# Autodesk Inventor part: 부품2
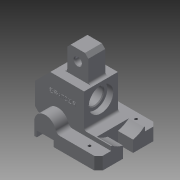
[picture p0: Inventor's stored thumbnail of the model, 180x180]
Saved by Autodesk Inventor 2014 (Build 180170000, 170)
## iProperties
Created: 2016-11
Part Number: 부품2
Material: 일반
Document SubType Name: Modeling
Designer: net
Density: 1 g/cm^3
Appearance: 기본값
Author: net
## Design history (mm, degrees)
sketch "스케치1"
  geometry: L1 (31, 18)-(-9, 18); L2 (-9, 18)-(-27, 0); L3 (-27, 0)-(-27, -30); L4 (-27, -30)-(31, -30); L5 (31, -30)-(31, 18); L6 (31, -10)-(31, -30); L7 (63, -22)-(31, -22); L8 (31, -22)-(31, -42); L9 (31, -42)-(63, -42); L10 (63, -42)-(63, -22); 1 further point
  constraints: 20 end point, 3 parallel, 3 perpendicular, 2 horizontal, 1 point on line
  dimensions: "d0" = 45 deg angle of L1 L2; "d1" = 30 distance from line of L4 point (0, 0); "d2" = 48 distance of L4.end L1.start; "d3" = 58 distance of L3.end L4.end; "d4" = 27 distance from line of point (0, 0) L3; "d5" = 18 horizontal distance of L1.end L2.end; "d31" = 42 distance from line of L9 point (0, 0); "d32" = 90 distance between parallel lines of L3 L10; "d33" = 20 distance of L9.end L7.start
extrude "돌출1" new body sketch "스케치1" stored distance "d6" = 40; taper "d7" = 0 deg
sketch "스케치2"
  geometry: L1 (-13, -27)-(-13, -42); L2 (-13, -42)-(-10, -42); L3 (-10, -42)-(-10, -35); L4 (-10, -35)-(10, -35); L5 (10, -35)-(10, -42); L6 (10, -42)-(63, -42); L7 (63, -42)-(63, -27); L8 (63, -27)-(17.292, -27); A1 r 13 centre (0, -27) between (12.488, -23.389) and (-13, -27); A2 r 5 centre (17.292, -22) between (12.488, -23.389) and (17.292, -27); 1 further point
  constraints: 16 end point, 5 parallel, 4 point on circle, 3 perpendicular, 3 tangent, 2 centre point, 1 horizontal alignment, 1 vertical, 1 vertical alignment
  dimensions: "d8" = 5 radius of A2; "d9" = 20 distance of L3.end L4.end; "d10" = 3 distance of L1.end L2.end; "d11" = 7 distance of L2.end L3.end; "d12" = 13 radius of A1; "d13" = 15 distance between parallel lines of L6 L8; "d14" = 63 distance from line of L7 A1.centre; "d15" = 42 distance from line of point (0, 0) L6
extrude "돌출2" join sketch "스케치2" stored distance "d16" = 70; taper "d17" = 0 deg
sketch "스케치3"
  geometry: L1 (63, -22)-(63, -42) reference; L2 (63, -42)-(10, -42) reference; L3 (10, -42)-(10, -35) reference; L4 (10, -35)-(-10, -35) reference; L5 (-10, -35)-(-10, -42) reference; L6 (-10, -42)-(-13, -42) reference; L7 (-13, -42)-(-13, -30) reference; L8 (-13, -30)-(-27, -30) reference; L9 (-27, -30)-(-27, 0) reference; L10 (-27, 0)-(-9, 18) reference; L11 (-9, 18)-(31, 18) reference; L12 (31, 18)-(31, -22) reference; L13 (1, 18)-(1, 44); L14 (1, 44)-(5, 48); L15 (5, 48)-(22, 48); L16 (22, 48)-(26, 44); L17 (26, 44)-(26, 18); L18 (31, -22)-(63, -22) reference; 1 further point
  constraints: 10 end point, 3 perpendicular, 2 point on line, 1 parallel
  dimensions: "d18" = 4 horizontal distance of L13.end L14.end; "d19" = 4 horizontal distance of L15.end L16.end; "d20" = 4 horizontal distance of L13.end L14.end; "d21" = 25 distance between parallel lines of L17 L13; "d22" = 5 distance between parallel lines of L17 L12; "d23" = 90 distance between parallel lines of L2 L15
extrude "돌출3" join sketch "스케치3" stored distance "d24" = 20; taper "d25" = 0 deg
sketch "스케치5"
  geometry: L1 (0, 0)-(40, 0) reference; L2 (55, -20)-(-15, -20) reference; L3 (14, -6.373)-(14, -20); L4 (26, -6.373)-(26, -20); A1 r 29 centre (20, 22) between (1.106, 0) and (14, -6.373); A2 r 29 centre (20, 22) between (26, -6.373) and (38.894, 0); 1 further point
  constraints: 4 end point, 4 point on circle, 4 point on line, 2 centre point, 2 perpendicular, 1 coincident
  dimensions: "d35" = 12 distance between parallel lines of L3 L4; "d36" = 6 distance from line of point (20, 22) L3; "d37" = 29 radius of A1; "d38" = 29 radius of A2
extrude "돌출4" cut sketch "스케치5" distance "d39" = 18; taper "d40" = 0 deg
sketch "스케치6"
  geometry: 1 further point
hole "구멍1" sketch "스케치6" at (-20, 22) diameter "d41" = 20; stored, may be unused: countersink angle "d45" = 90 deg, drill point angle "d47" = 118 deg; dims "d42" = 6, "d43" = 29, "d44" = 7, "d46" = 8
sketch "스케치7"
  geometry: L1 (1, 44)-(1, 18) reference; 2 further points
  dimensions: "d48" = 12.5 distance from line of point (13.5, 35) L1; "d49" = 35 vertical distance of point (0, 0) point (13.5, 35)
hole "구멍2" sketch "스케치7" at (13.5, 35) diameter "d50" = 8; stored, may be unused: countersink angle "d54" = 90 deg, drill point angle "d56" = 118 deg; dims "d51" = 6, "d52" = 29, "d53" = 7, "d55" = 8
chamfer "모따기1" distance "d57" = 4; stored, may be unused: second distance "d58" = 2, angle "d59" = 45 deg
chamfer "모따기2" distance "d60" = 1; stored, may be unused: second distance "d61" = 2, angle "d62" = 45 deg
chamfer "모따기3" distance "d63" = 5; stored, may be unused: second distance "d64" = 2, angle "d65" = 45 deg
sketch "스케치8"
  geometry: L1 (45.708, -10)-(45.708, 0) reference; 3 further points
  constraints: 1 vertical alignment
  dimensions: "d66" = 55 distance of point (27.708, -7.5) point (27.708, 47.5); "d67" = 27.5 vertical distance of point (-17.292, 20) point (27.708, 47.5); "d68" = 18 distance from line of L1 point (27.708, -7.5)
hole "구멍3" sketch "스케치8" at (27.708, -7.5), (27.708, 47.5) diameter "d69" = 3.242; stored, may be unused: countersink angle "d73" = 90 deg, drill point angle "d75" = 118 deg; dims "d70" = 20, "d71" = 29, "d72" = 7, "d74" = 8
fillet "모깎기1" dims "d76" = 3
sketch "스케치9"
  geometry: L1 (31, -19)-(31, 18) reference; L2 (31, 18)-(-9, 18) reference; 2 further points
  constraints: 1 other
  dimensions: "d77" = 18 distance from line of L2 point (6, 0); "d78" = 25 distance from line of point (6, 0) L1
feature "엠보싱1" sketch "스케치9" dims "d0" = 45 deg, "d1" = 30, "d2" = 48, "d3" = 58, "d4" = 27, "d5" = 18, "d31" = 42, "d32" = 90, "d33" = 20, "d79" = 0.5, "d80" = 0
node "솔리드1"
node "절단 모서리 투영1"
other parameters: "d34" = 58
